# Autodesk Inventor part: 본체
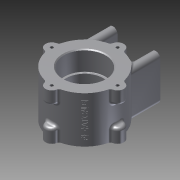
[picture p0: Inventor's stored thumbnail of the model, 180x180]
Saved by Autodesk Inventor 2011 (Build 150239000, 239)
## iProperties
Created: 2015-03
Part Number: 본체
Document SubType Name: Modeling
Designer: LINEART07
Density: 1 g/cm^3
Author: LINEART07
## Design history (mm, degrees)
sketch "스케치5"
  geometry: C1 r 37 at (0, 0); 1 further point
  constraints: 1 centre point, 1 coincident
  dimensions: "d17" = 74 diameter of C1
extrude "돌출4" new body sketch "스케치5" distance "d18" = 52; taper "d19" = 0 deg
sketch "스케치6"
  geometry: A1 r 37 centre (0, 0) between (-6.969, 36.338) and (6.969, 36.338) reference; A2 r 7 centre (0, 37) between (6.969, 36.338) and (-6.969, 36.338)
  constraints: 4 point on circle, 1 centre point
  dimensions: "d20" = 7 radius of A2
extrude "돌출5" join sketch "스케치6" distance "d21" = 15; taper "d22" = 0 deg
sketch "스케치7"
  geometry: A1 r 7 centre (0, 37) between (6.969, 36.338) and (-6.969, 36.338) reference; A2 r 37 centre (0, 0) between (6.969, 36.338) and (-6.969, 36.338) reference; A3 r 7 centre (0, 37) between (6.969, 36.338) and (-6.969, 36.338)
  constraints: 4 point on circle, 1 centre point, 1 coincident
extrude "돌출6" join sketch "스케치7" distance "d26" = 15; taper "d27" = 0 deg
node "작업 평면2"
sketch "스케치8"
  geometry: L1 (-36.338, 52)-(-6.969, 52) reference; L2 (7, 52)-(-7, 52) reference; L3 (-7, 0)-(7, 0) reference; L4 (0, 0)-(0, 52); L5 (-24, 58.838)-(-24, -13.337); L6 (-55.49, 46)-(59.857, 46); L7 (-59.657, 6)-(61.023, 6); L8 (0, 26)-(-59.491, 26) reference; L9 (-29, 46)-(-29, 6); L10 (-19, 6)-(-19, 46); A1 r 5 centre (-24, 46) between (-19, 46) and (-29, 46); A2 r 5 centre (-24, 6) between (-29, 6) and (-19, 6); 3 further points
  constraints: 14 end point, 8 point on line, 4 point on circle, 3 parallel, 2 centre point, 2 midpoint, 2 perpendicular, 1 horizontal
  dimensions: "d32" = 24 distance between parallel lines of L4 L5; "d33" = 20 distance between parallel lines of L7 L8; "d34" = 20 distance between parallel lines of L6 L8
extrude "돌출7" join sketch "스케치8" stored distance "d35" = 15; taper "d36" = 0 deg
sketch "스케치9"
  geometry: L1 (-6.969, 15)-(6.969, 15) reference; L2 (6.969, 0)-(6.969, 15) reference; L3 (-6.969, 0)-(6.969, 0) reference; L4 (-6.969, 15)-(-6.969, 0) reference; L5 (31.749, 6)-(31.749, 46) reference; L6 (22.978, 46)-(22.978, 6) reference; L7 (31.749, 46)-(31.749, 6) reference; L8 (22.978, 6)-(22.978, 46) reference; L9 (6.969, 52)-(6.969, 37) reference; L10 (6.969, 37)-(-6.969, 37) reference; L11 (-6.969, 37)-(-6.969, 52) reference; L12 (-6.969, 52)-(-36.338, 52) reference; L13 (-36.338, 52)-(-36.338, 37) reference; L14 (-36.338, 37)-(-36.338, 37) reference; L15 (-36.338, 37)-(-36.338, 52) reference; L16 (-36.338, 52)-(-6.969, 52) reference; L17 (-6.969, 52)-(-6.969, 37) reference; L18 (-6.969, 37)-(6.969, 37) reference; L19 (6.969, 37)-(6.969, 52) reference; L20 (6.969, 52)-(36.338, 52) reference; L21 (36.338, 52)-(36.338, 37) reference; L22 (36.338, 37)-(36.338, 37) reference; L23 (36.338, 37)-(36.338, 52) reference; L24 (36.338, 52)-(6.969, 52) reference; L25 (-6.969, 0)-(-6.969, 15) reference; L26 (-6.969, 15)-(6.969, 15) reference; L27 (6.969, 15)-(6.969, 0) reference; L28 (36.338, 0)-(6.969, 0) reference; L29 (36.338, 0)-(36.338, 15) reference; L30 (36.338, 15)-(36.338, 15) reference; L31 (36.338, 15)-(36.338, 0) reference; L32 (6.969, 0)-(36.338, 0) reference; L33 (6.969, 0)-(6.969, 15) reference; L34 (6.969, 15)-(-6.969, 15) reference; L35 (-6.969, 15)-(-6.969, 0) reference; L36 (-36.338, 0)-(-6.969, 0) reference; L37 (-36.338, 0)-(-36.338, 15) reference; L38 (-36.338, 15)-(-36.338, 15) reference; L39 (-36.338, 15)-(-36.338, 0) reference; L40 (-6.969, 0)-(-36.338, 0) reference; L41 (6.969, 37)-(-6.969, 37) reference; L42 (-6.969, 52)-(-6.969, 37) reference; L43 (6.969, 52)-(-6.969, 52) reference; L44 (6.969, 37)-(6.969, 52) reference; L45 (0, -9.9)-(0, 64.335) reference; L46 (0, 0)-(-23.5, 0); L47 (-23.5, 0)-(-23.5, 22); L48 (-23.5, 22)-(0, 22); L49 (0, 22)-(0, 0); L50 (0, 52)-(-23.5, 52); L51 (-23.5, 52)-(-23.5, 30); L52 (-23.5, 30)-(0, 30); L53 (0, 30)-(0, 52); L54 (0, 22)-(-21, 22); L55 (-21, 22)-(-21, 30); L56 (-21, 30)-(0, 30); L57 (0, 30)-(0, 22)
  constraints: 26 end point, 7 parallel, 4 horizontal alignment, 3 horizontal, 3 perpendicular, 2 point on line, 1 midpoint, 1 vertical
  dimensions: "d82" = 23.5 distance between parallel lines of L45 L47; "d83" = 23.5 distance between parallel lines of L53 L51; "d84" = 22 distance between parallel lines of L54 L46; "d85" = 22 distance between parallel lines of L50 L56
revolve "회전1" sketch "스케치9" stored, may be unused: angle "d37" = 90 deg
sketch "스케치10"
  geometry: A1 r 7 centre (-37, 0) between (-36.338, 6.969) and (-36.338, -6.969) reference; 1 further point
  constraints: 1 coincident
hole "Hole1" sketch "스케치10" at (-37, 0) diameter "d38" = 3.242; stored, may be unused: countersink angle "d42" = 90 deg, drill point angle "d44" = 118 deg; dims "d39" = 8, "d40" = 4, "d41" = 2, "d43" = 11
sketch "스케치11"
  geometry: A1 r 7 centre (0, -37) between (-6.969, -36.338) and (6.969, -36.338) reference; 1 further point
  constraints: 1 coincident
hole "Hole2" sketch "스케치11" at (0, -37) diameter "d48" = 3.242; stored, may be unused: countersink angle "d52" = 90 deg, drill point angle "d54" = 118 deg; dims "d49" = 8, "d50" = 4, "d51" = 2, "d53" = 11
sketch "스케치12"
  geometry: A1 r 5 centre (24, -6) between (29, -6) and (19, -6) reference; A2 r 5 centre (24, -46) between (19, -46) and (29, -46) reference; 3 further points
  constraints: 2 coincident
hole "Hole4" sketch "스케치12" at (24, -6), (24, -46) diameter "d65" = 4.134; stored, may be unused: countersink angle "d69" = 90 deg, drill point angle "d71" = 118 deg; dims "d66" = 6, "d67" = 4, "d68" = 2, "d70" = 8
fillet "모깎기1" dims "d72" = 0.3
fillet "모깎기2" dims "d73" = 3
fillet "모깎기3" dims "d74" = 3
chamfer "모따기1" distance "d75" = 1; stored, may be unused: second distance "d76" = 2, angle "d77" = 45 deg
node "작업 평면6"
  node "작업 평면5"
sketch "스케치15"
  geometry: L1 (36.628, 46)-(36.628, 6) reference; L2 (36.976, 52)-(31.796, 52) reference; L3 (31.796, 40)-(31.796, 52) reference; L4 (24.303, 34)-(27.899, 34) reference; L5 (18.921, 52)-(18.921, 40) reference; L6 (18.921, 52)-(-18.921, 52) reference; L7 (-18.921, 40)-(-18.921, 52) reference; L8 (-27.899, 34)-(-24.303, 34) reference; L9 (-31.796, 52)-(-31.796, 40) reference; L10 (-31.796, 52)-(-31.796, 52) reference; L11 (-31.796, 40)-(-31.796, 52) reference; L12 (-24.303, 34)-(-27.899, 34) reference; L13 (-18.921, 52)-(-18.921, 40) reference; L14 (-18.921, 52)-(-1.342, 52) reference; L15 (-5.233, 6)-(-5.233, 46) reference; L16 (-18.921, 0)-(-1.342, 0) reference; L17 (-18.921, 12)-(-18.921, 0) reference; L18 (-27.899, 18)-(-24.303, 18) reference; L19 (-31.796, 0)-(-31.796, 12) reference; L20 (-31.796, 0)-(-31.796, 0) reference; L21 (-31.796, 12)-(-31.796, 0) reference; L22 (-24.303, 18)-(-27.899, 18) reference; L23 (-18.921, 0)-(-18.921, 12) reference; L24 (18.921, 0)-(-18.921, 0) reference; L25 (18.921, 12)-(18.921, 0) reference; L26 (27.899, 18)-(24.303, 18) reference; L27 (31.796, 0)-(31.796, 12) reference; L28 (36.976, 0)-(31.796, 0) reference; L29 (-37, 0)-(-37, 52) reference; L30 (0, 0)-(0, 52); 4 further points
  constraints: 3 midpoint, 2 end point, 1 coincident, 1 horizontal alignment, 1 parallel, 1 vertical alignment, 17 other
  node "투영된 루프5"
sketch "스케치16"
  geometry: 1 further point
feature "엠보싱1" dims "d26" = 15, "d80" = 0.5, "d81" = 0
node "솔리드2"
pattern_circular "원형 패턴2" dims angle "d24" = 360 deg
pattern_circular "원형 패턴3" dims angle "d29" = 360 deg
mirror "대칭1"
pattern_circular "원형 패턴4" dims angle "d46" = 360 deg
pattern_circular "원형 패턴5" dims angle "d56" = 360 deg
mirror "대칭2"
node "투영된 루프1"
node "투영된 루프2"
node "투영된 루프3"
node "투영된 루프4"
node "작업축1"
other parameters: "d31" = 56, "d78" = 45 deg
